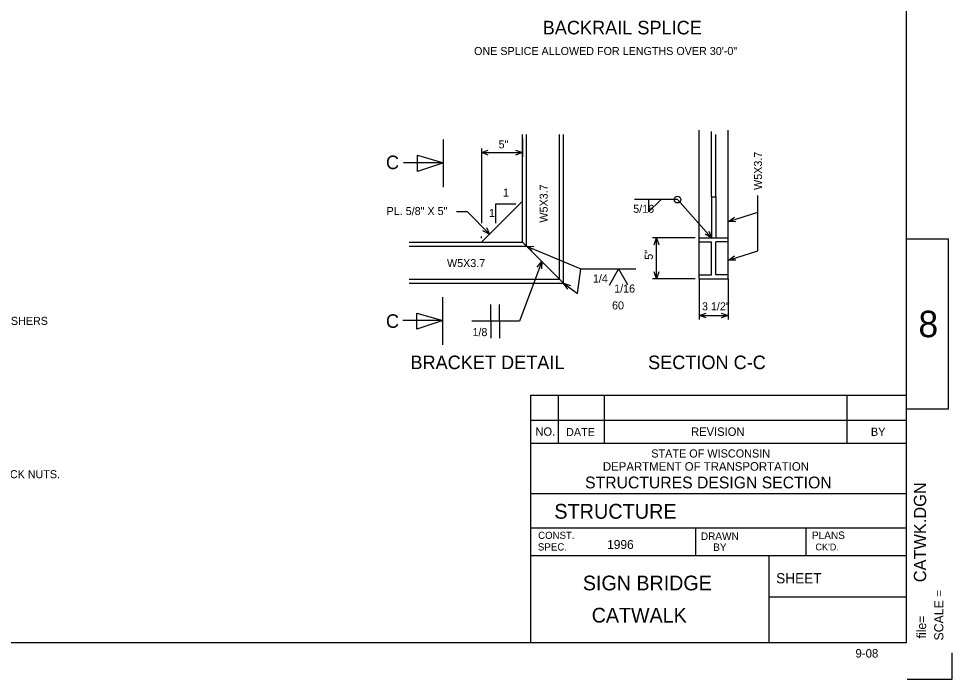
# Model space of a CAD drawing. Extents: x 2472.79 to 2482.44, y 2457.5 to 2462.64.
# Drawn here: x 2479.554 to 2482.227, y 2457.716 to 2459.607 of the extents above; entities that cross this region are included whole.
import ezdxf

# ---------------------------------------------------------------- set-up
doc = ezdxf.new("R2010")
doc.units = 0
doc.layers.add('Level 1', color=7, linetype='Continuous')
doc.layers.add('Level 2', color=7, linetype='Continuous')

msp = doc.modelspace()

# ---------------------------------------------------------------- linework, layer by layer
at = {"layer": 'Level 1'}
for p, q in [((2482.0963, 2457.8211), (2482.0963, 2462.2306)), ((2481.5028, 2458.8736), (2481.5028, 2459.2883)), ((2481.5852, 2458.8736), (2481.5852, 2459.2883)), ((2480.7698, 2459.1253), (2480.7698, 2459.2617)), ((2480.9963, 2458.9677), (2480.9963, 2459.276)), ((2481.0076, 2458.9564), (2481.0076, 2459.276)), ((2481.1027, 2458.8613), (2481.1027, 2459.276)), ((2481.1139, 2458.8501), (2481.1139, 2459.276)), ((2481.5381, 2459.0975), (2481.5381, 2459.2839)), ((2481.5498, 2459.0975), (2481.5498, 2459.2756)), ((2480.6953, 2459.2163), (2480.7698, 2459.1948)), ((2480.6953, 2459.1699), (2480.6953, 2459.2163)), ((2480.7698, 2459.1948), (2480.6556, 2459.1948)), ((2480.7698, 2459.1948), (2480.6953, 2459.1699)), ((2480.9963, 2459.0853), (2480.8786, 2458.9677)), ((2481.5381, 2459.0975), (2481.5498, 2459.0975)), ((2481.5381, 2459.0975), (2481.5381, 2458.9799)), ((2481.5498, 2459.0975), (2481.5498, 2458.9799)), ((2480.6721, 2458.9677), (2480.9963, 2458.9677)), ((2480.9963, 2458.9677), (2481.1139, 2458.8501)), ((2481.5028, 2458.9799), (2481.5852, 2458.9799)), ((2481.5028, 2458.9686), (2481.5028, 2458.9799)), ((2481.5028, 2458.9686), (2481.5381, 2458.9686)), ((2481.5381, 2458.8736), (2481.5381, 2458.9686)), ((2481.5498, 2458.8736), (2481.5498, 2458.9686)), ((2481.5852, 2458.9686), (2481.5498, 2458.9686)), ((2481.5852, 2458.9686), (2481.5852, 2458.9799)), ((2480.6721, 2458.9564), (2481.0076, 2458.9564)), ((2480.6721, 2458.8613), (2481.1027, 2458.8613)), ((2481.5028, 2458.8623), (2481.5028, 2458.8736)), ((2481.5028, 2458.8736), (2481.5381, 2458.8736)), ((2481.5028, 2458.8623), (2481.5852, 2458.8623)), ((2481.5852, 2458.8736), (2481.5498, 2458.8736)), ((2481.5852, 2458.8623), (2481.5852, 2458.8736)), ((2480.6721, 2458.8501), (2481.1139, 2458.8501)), ((2480.768, 2458.6734), (2480.768, 2458.8099)), ((2480.6935, 2458.7645), (2480.768, 2458.7429)), ((2480.6935, 2458.7181), (2480.6935, 2458.7645)), ((2480.768, 2458.7429), (2480.6538, 2458.7429)), ((2480.768, 2458.7429), (2480.6935, 2458.7181)), ((2481.0203, 2458.5297), (2482.097, 2458.5297)), ((2481.0203, 2458.392), (2481.0203, 2458.5297)), ((2481.0998, 2458.392), (2481.0998, 2458.5297)), ((2481.231, 2458.392), (2481.231, 2458.5297)), ((2481.9264, 2458.392), (2481.9264, 2458.5297)), ((2481.0203, 2458.4576), (2482.097, 2458.4576)), ((2481.0203, 2457.8211), (2481.0203, 2458.392)), ((2481.0203, 2458.392), (2482.097, 2458.392)), ((2481.0203, 2458.2477), (2482.097, 2458.2477)), ((2481.0203, 2458.1493), (2482.097, 2458.1493)), ((2481.4928, 2458.0705), (2481.4928, 2458.1493)), ((2481.8092, 2458.0705), (2481.8092, 2458.1493)), ((2481.0203, 2458.0705), (2482.097, 2458.0705)), ((2481.7026, 2457.8211), (2481.7026, 2458.0705)), ((2481.7028, 2457.9524), (2482.0963, 2457.9524)), ((2475.5081, 2457.8211), (2482.0963, 2457.8211)), ((2482.2275, 2457.7161), (2482.2275, 2457.7923)), ((2482.0978, 2457.7161), (2482.2275, 2457.7161))]:
    msp.add_line(p, q, dxfattribs=at)
msp.add_lwpolyline([(2482.0963, 2458.977), (2482.2154, 2458.977), (2482.2154, 2458.4896), (2482.0963, 2458.4896)], close=True, dxfattribs=at)
at = {"layer": 'Level 2'}
for p, q in [((2480.9963, 2459.2642), (2480.9963, 2459.212)), ((2480.8786, 2459.2355), (2480.8786, 2459.0217)), ((2480.8786, 2459.2237), (2480.8985, 2459.2306)), ((2480.8786, 2459.2237), (2480.9963, 2459.2237)), ((2480.8985, 2459.2169), (2480.8786, 2459.2237)), ((2480.9764, 2459.2306), (2480.9963, 2459.2237)), ((2480.9963, 2459.2237), (2480.9764, 2459.2169)), ((2481.6701, 2458.9429), (2481.6701, 2459.101)), ((2480.9201, 2459.0217), (2480.9201, 2459.0772)), ((2480.9201, 2459.0772), (2480.9778, 2459.0772)), ((2481.4403, 2459.0892), (2481.3175, 2459.0892)), ((2481.3578, 2459.0892), (2481.3578, 2459.0542)), ((2481.3578, 2459.0542), (2481.3923, 2459.0886)), ((2481.5381, 2458.9799), (2481.4403, 2459.0892)), ((2480.8387, 2459.0539), (2480.8072, 2459.0539)), ((2480.902, 2458.9902), (2480.8387, 2459.0539)), ((2481.5864, 2459.0264), (2481.6701, 2459.0531)), ((2481.5864, 2459.0264), (2481.6033, 2459.039)), ((2481.6075, 2459.0259), (2481.5864, 2459.0264)), ((2480.902, 2458.9902), (2480.8831, 2458.9995)), ((2480.8929, 2459.0091), (2480.902, 2458.9902)), ((2481.5299, 2458.9993), (2481.5381, 2458.9799)), ((2480.8786, 2458.9794), (2480.8786, 2458.9836)), ((2481.491, 2458.9799), (2481.3684, 2458.9799)), ((2481.3733, 2458.9601), (2481.3802, 2458.9799)), ((2481.3802, 2458.8623), (2481.3802, 2458.9799)), ((2481.3802, 2458.9799), (2481.387, 2458.9601)), ((2481.5381, 2458.9799), (2481.5197, 2458.9902)), ((2481.0076, 2458.9564), (2481.1635, 2458.8912)), ((2481.0076, 2458.9564), (2481.0286, 2458.955)), ((2481.0233, 2458.9424), (2481.0076, 2458.9564)), ((2481.5864, 2458.9161), (2481.6701, 2458.9429)), ((2481.5864, 2458.9161), (2481.6033, 2458.9287)), ((2481.6075, 2458.9157), (2481.5864, 2458.9161)), ((2481.0519, 2458.9119), (2480.9878, 2458.741)), ((2481.0384, 2458.8957), (2481.0519, 2458.9119)), ((2481.0519, 2458.9119), (2481.0513, 2458.8909)), ((2481.1537, 2458.8209), (2481.1635, 2458.8912)), ((2481.1635, 2458.8912), (2481.3212, 2458.8912)), ((2481.2716, 2458.8908), (2481.2443, 2458.8434)), ((2481.2716, 2458.8908), (2481.2974, 2458.8462)), ((2481.491, 2458.8623), (2481.3684, 2458.8623)), ((2481.3802, 2458.8623), (2481.3733, 2458.8822)), ((2481.387, 2458.8822), (2481.3802, 2458.8623)), ((2481.5028, 2458.8619), (2481.5028, 2458.746)), ((2481.5852, 2458.8619), (2481.5852, 2458.746)), ((2481.1139, 2458.8501), (2481.1537, 2458.8209)), ((2481.1139, 2458.8501), (2481.134, 2458.8438)), ((2481.1259, 2458.8327), (2481.1139, 2458.8501)), ((2480.9057, 2458.741), (2480.9057, 2458.7889)), ((2480.9303, 2458.741), (2480.9303, 2458.7889)), ((2481.5028, 2458.7577), (2481.5227, 2458.7646)), ((2481.5028, 2458.7577), (2481.5852, 2458.7577)), ((2481.5227, 2458.7509), (2481.5028, 2458.7577)), ((2481.5653, 2458.7646), (2481.5852, 2458.7577)), ((2481.5852, 2458.7577), (2481.5653, 2458.7509)), ((2480.9878, 2458.741), (2480.8515, 2458.741)), ((2480.9057, 2458.741), (2480.9057, 2458.693)), ((2480.9303, 2458.741), (2480.9303, 2458.693))]:
    msp.add_line(p, q, dxfattribs=at)
msp.add_ellipse((2481.4403, 2459.0892), major_axis=(0.00951, 0), ratio=0.9996, dxfattribs=at)

# ---------------------------------------------------------------- texts
at = {"layer": 'Level 1'}
for s, height, p in [('8', 0.0758, (2482.1305, 2458.6954)), ('NO.', 0.02392, (2481.0333, 2458.4133)), ('DATE', 0.02328, (2481.1209, 2458.4123)), ('REVISION', 0.02397, (2481.4792, 2458.413)), ('BY', 0.02327, (2481.9944, 2458.413)), ('STATE OF WISCONSIN', 0.023257, (2481.3652, 2458.351)), ('DEPARTMENT OF TRANSPORTATION', 0.024447, (2481.2267, 2458.3132)), ('STRUCTURES DESIGN SECTION', 0.033701, (2481.1758, 2458.2627)), ('STRUCTURE', 0.04247, (2481.0876, 2458.1758)), ('CONST.', 0.02065, (2481.0412, 2458.118)), ('PLANS', 0.02149, (2481.8255, 2458.1177)), ('1996', 0.02558, (2481.2388, 2458.0892)), ('1996', 0.02558, (2481.2389, 2458.0892)), ('DRAWN', 0.02147, (2481.5074, 2458.115)), ('SPEC.', 0.02084, (2481.0404, 2458.0848)), ('BY', 0.02142, (2481.5426, 2458.0836)), ("CK'D.", 0.01946, (2481.8354, 2458.0852)), ('SHEET', 0.02912, (2481.723, 2457.9909)), ('9-08', 0.0244, (2481.9502, 2457.7783))]:
    msp.add_text(s, height=height, dxfattribs=at).set_placement(p)
for s, height, p in [('CATWK.DGN', 0.035, (2482.1524, 2457.994)), ('SCALE =          ', 0.026247, (2482.2019, 2457.8272)), ('file=                      ', 0.026247, (2482.1524, 2457.8331))]:
    msp.add_text(s, height=height, rotation=90, dxfattribs=at).set_placement(p)
at = {"layer": 'Level 2'}
for s, height, p in [('BACKRAIL SPLICE', 0.0388, (2481.0544, 2459.5623)), ('ONE SPLICE ALLOWED FOR LENGTHS OVER 30\'-0"', 0.023, (2480.8578, 2459.5032)), ('5"', 0.023, (2480.928, 2459.236)), ('C', 0.0388, (2480.6054, 2459.1765)), ('1', 0.023, (2480.9405, 2459.0981)), ('5/16', 0.023, (2481.3135, 2459.0515)), ('PL. 5/8" X 5"', 0.023, (2480.6073, 2459.0451)), ('1', 0.023, (2480.9005, 2459.0398)), ('W5X3.7', 0.023, (2480.7803, 2458.8961)), ('1/4', 0.023, (2481.1981, 2458.852)), ('1/16', 0.023, (2481.259, 2458.8232)), ('60', 0.023, (2481.2529, 2458.775)), ('3 1/2"', 0.023, (2481.5105, 2458.7723)), ('ALUM. WASHERS', 0.023, (2479.3792, 2458.7307)), ('C', 0.0388, (2480.6054, 2458.7222)), ('1/8', 0.023, (2480.8532, 2458.6985)), ('BRACKET DETAIL', 0.0388, (2480.6755, 2458.604)), ('SECTION C-C', 0.0388, (2481.3561, 2458.604)), ('ALUM. LOCK NUTS.', 0.023, (2479.3848, 2458.2918)), ('SIGN BRIDGE ', 0.0421, (2481.1694, 2457.9708)), (' CATWALK', 0.0421, (2481.1791, 2457.8786))]:
    msp.add_text(s, height=height, dxfattribs=at).set_placement(p)
for s, p in [('W5X3.7', (2481.6824, 2459.117)), ('W5X3.7', (2481.0686, 2459.0234)), ('5"', (2481.3698, 2458.9171))]:
    msp.add_text(s, height=0.023, rotation=90, dxfattribs=at).set_placement(p)

doc.saveas('drawing.dxf')
